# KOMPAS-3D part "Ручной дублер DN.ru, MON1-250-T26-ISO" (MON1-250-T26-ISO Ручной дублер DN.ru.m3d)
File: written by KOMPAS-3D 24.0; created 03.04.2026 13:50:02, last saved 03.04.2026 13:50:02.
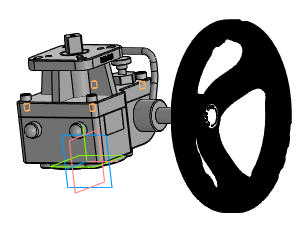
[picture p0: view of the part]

Document properties: Автор: R2D2; Полное имя файла: E:\Работа\Зайцев\Аксессуары для пневмоприводов\Ручной дублер DN.ru\MON1-250-T26-ISO Ручной дублер DN.ru\исходные материалы\MON1-250-T26-ISO Ручной дублер DN.ru.m3d

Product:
- Component [detail]: Деталь1  | qty 1  | pos. 1  | Масса: 5.630796; Автор: R2D2; additional columns: Типовые; source file: 3.m3d
- Component [detail]: Деталь1  | qty 1  | pos. 1  | Масса: 5.630796; Автор: R2D2; additional columns: Типовые; source file: 2.m3d
- Component [detail]: Деталь1  | qty 1  | pos. 1  | Масса: 5.630796; Автор: R2D2; additional columns: Типовые; source file: 1.m3d
- Component [detail]: Деталь 2  | qty 1  | pos. 2  | Масса: 1.734021; Автор: R2D2; additional columns: Типовые; source file: Деталь 2 Деталь 2.m3d
- Component [standard]: Hexagon socket head cap screw ISO 4762 - М6 x 10  | qty 4  | Материал: Не определено (density 0 kg/m3); Масса: 0.0047; Раздел спецификации: Стандартные изделия; Рассекать на разрезах: no
- Part/product: Ручной дублер DN.ru  | designation MON1-250-T26-ISO
    Масса: 3
    Раздел спецификации: Прочие изделия
    Примечание: D290-00336

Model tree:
1. Эскиз:2  (with: Грань.Операция без истории:1, Ребро.Операция без истории:1)
2. Элемент выдавливания:3
     Расстояние 2 = 10
3. Эскиз:3  (with: Грань.Операция без истории:1, Ребро.Операция без истории:1)
4. Элемент выдавливания:4  (with: Грань.Операция без истории:1, Грань.Элемент выдавливания:4)  (labels: Грань.Твердое тело1)
     Расстояние 2 = 13; Расстояние = -10; Расстояние = -120; Расстояние = -145

Referenced files in E:\Работа\Зайцев\Аксессуары для пневмоприводов\Ручной дублер DN.ru\MON1-250-T26-ISO Ручной дублер DN.ru\исходные материалы\: 3.m3d, 2.m3d, 1.m3d, Деталь 2 Деталь 2.m3d
Referenced files in C:\Program Files\ASCON\KOMPAS-3D v24\Libs\PolynomLib\DATA\vault\Methods\Kompas\3D\: PLib_Screw_DIN_7984_1500.m3d
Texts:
  BOSimple***PART:86906dfe-320b-4a65-fedb-73bd2ba9e651***SHORTLOC:A259_235BDFABBEFC4171[1;10;6;-;Undefined]
  MON1-250-T26-ISO
  Деталь1 Деталь1
  Деталь 2 Деталь 2
  Hexagon socket head cap screw ISO 4762 - М6 x 10 (1)
  Hexagon socket head cap screw ISO 4762 - М6 x 10 (2)
  Hexagon socket head cap screw ISO 4762 - М6 x 10 (4)
  Hexagon socket head cap screw ISO 4762 - М6 x 10 (6)
  Плоскость ZX.Начало координат
  Ось Y.Начало координат
  Плоскость XY.Начало координат
  Плоскость ZY.Начало координат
